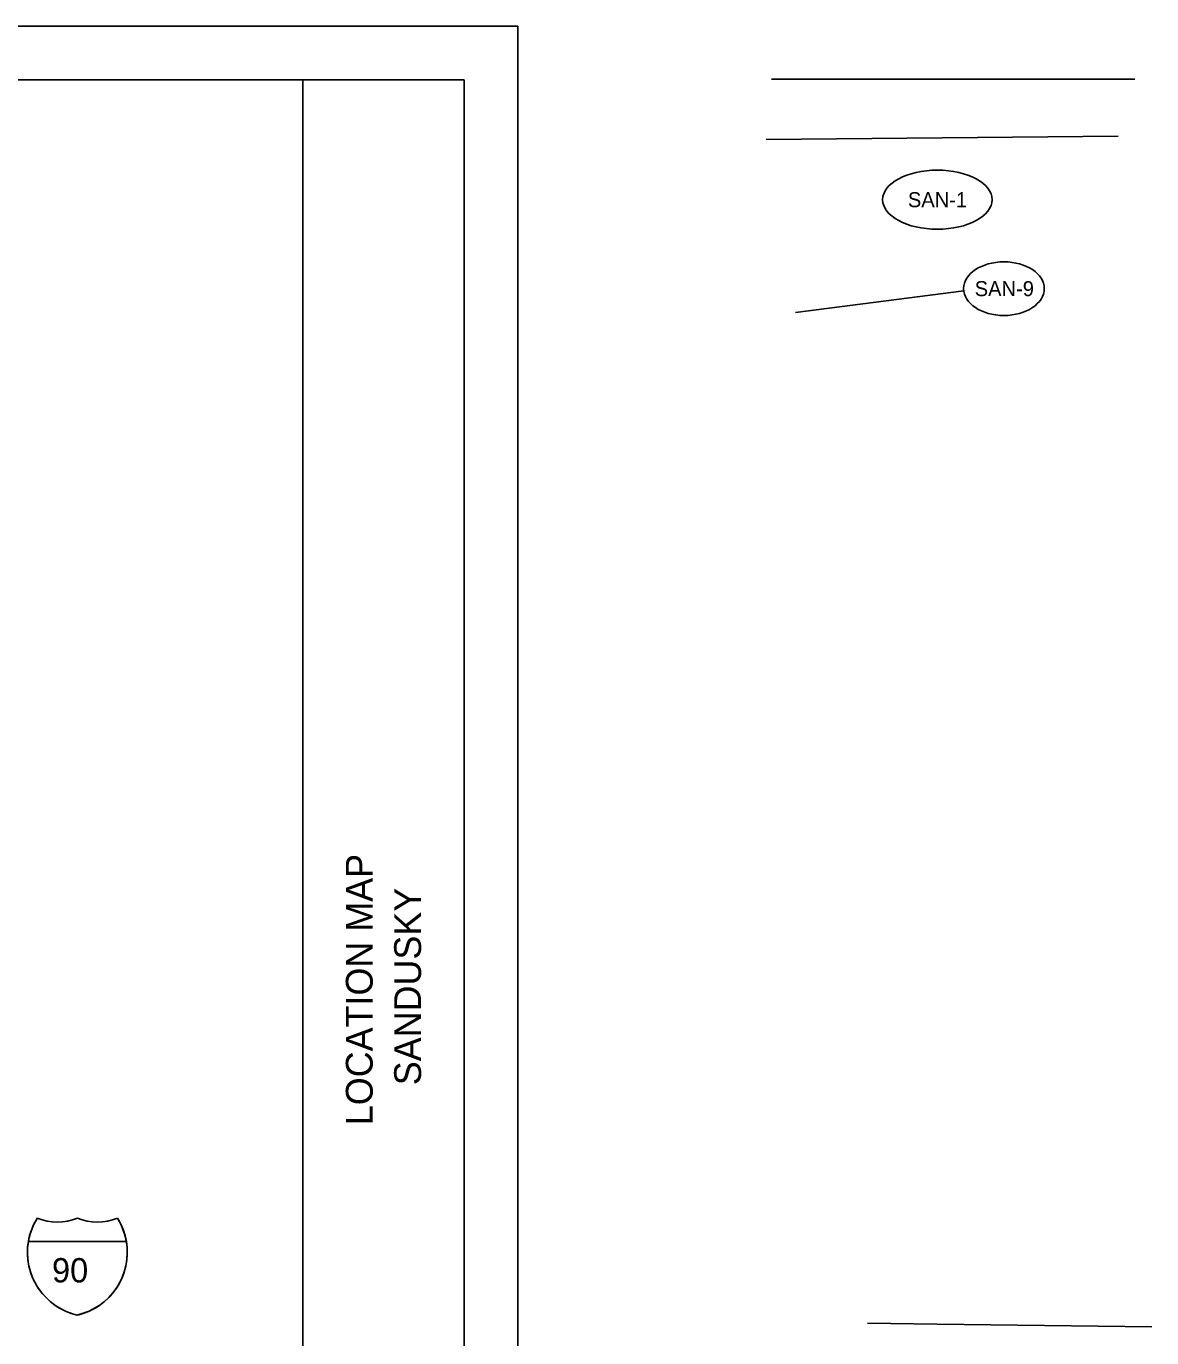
# Model space of a CAD drawing. Extents: x 0 to 798, y 0 to 440.
# Drawn here: x 588.5 to 798.1, y 195.7 to 440 of the extents above; entities that cross this region are included whole.
import ezdxf

# ---------------------------------------------------------------- set-up
doc = ezdxf.new("R2010")
doc.units = 0
for name, color, linetype in [('PV_P_Text', 7, 'Continuous'), ('RD_P_Fence', 7, 'Continuous'), ('SH_Border', 7, 'Continuous'), ('SH_Cut_Line', 7, 'Continuous'), ('SH_Data', 7, 'Continuous')]:
    doc.layers.add(name, color=color, linetype=linetype)

msp = doc.modelspace()

# ---------------------------------------------------------------- linework, layer by layer
at = {"layer": 'PV_P_Text'}
for p, q in [((588.88, 213.61), (607.13, 213.61)), ((607.13, 213.61), (588.88, 213.61)), ((607.13, 213.61), (588.88, 213.61))]:
    msp.add_line(p, q, dxfattribs=at)
for centre, radius, start, end in [((600.7, 211.6), 11.99, 147.8216, 256.9941), ((599.96, 211.81), 11.22, 146.654, 170.759), ((594.28, 226.8), 9.57, 247.0848, 292.9105), ((594.28, 226.8), 9.57, 247.0848, 292.9105), ((595.31, 211.6), 11.99, 283.0065, 32.1787), ((601.73, 226.8), 9.57, 247.0916, 292.9084), ((601.73, 226.8), 9.57, 247.0916, 292.9084), ((595.31, 211.6), 11.99, 9.6475, 32.179), ((600.7, 211.6), 11.99, 170.3514, 256.9967), ((595.33, 211.6), 11.97, 282.7667, 9.6898)]:
    msp.add_arc(centre, radius, start, end, dxfattribs=at)
at = {"layer": 'RD_P_Fence'}
for p, q in [((727.27, 430.12), (794.92, 430.12)), ((726.24, 418.92), (791.81, 419.55)), ((729.1, 418.95), (729.1, 418.95))]:
    msp.add_line(p, q, dxfattribs=at)
msp.add_lwpolyline([(745.13, 198.42), (758.13, 198.25), (798.06, 197.73)], dxfattribs=at)
at = {"layer": 'SH_Border'}
msp.add_line((640, 10), (640, 430), dxfattribs=at)
msp.add_lwpolyline([(30, 430), (670, 430), (670, 10), (30, 10)], close=True, dxfattribs=at)
at = {"layer": 'SH_Cut_Line'}
msp.add_lwpolyline([(0, 0), (680, 0), (680, 440), (0, 440)], close=True, dxfattribs=at)
at = {"layer": 'SH_Data'}
msp.add_line((763.06, 390.7), (731.73, 386.67), dxfattribs=at)
for centre, major_axis, ratio in [((758.14, 407.69), (10.19, 0), 0.540219), ((770.53, 391.12), (7.5, 0), 0.666667)]:
    msp.add_ellipse(centre, major_axis=major_axis, ratio=ratio, dxfattribs=at)

# ---------------------------------------------------------------- texts
at = {"layer": 'PV_P_Text'}
msp.add_text('90', height=4.528, dxfattribs=at).set_placement((593.29, 206))
at = {"layer": 'SH_Data'}
for s, p in [('SAN-1', (752.65, 406.29)), ('SAN-9', (765.09, 389.72))]:
    msp.add_text(s, height=2.8, dxfattribs=at).set_placement(p)
for s, p in [('LOCATION MAP', (653, 235.29)), ('SANDUSKY', (662, 242.73))]:
    msp.add_text(s, height=5, rotation=90, dxfattribs=at).set_placement(p)

doc.saveas('drawing.dxf')
